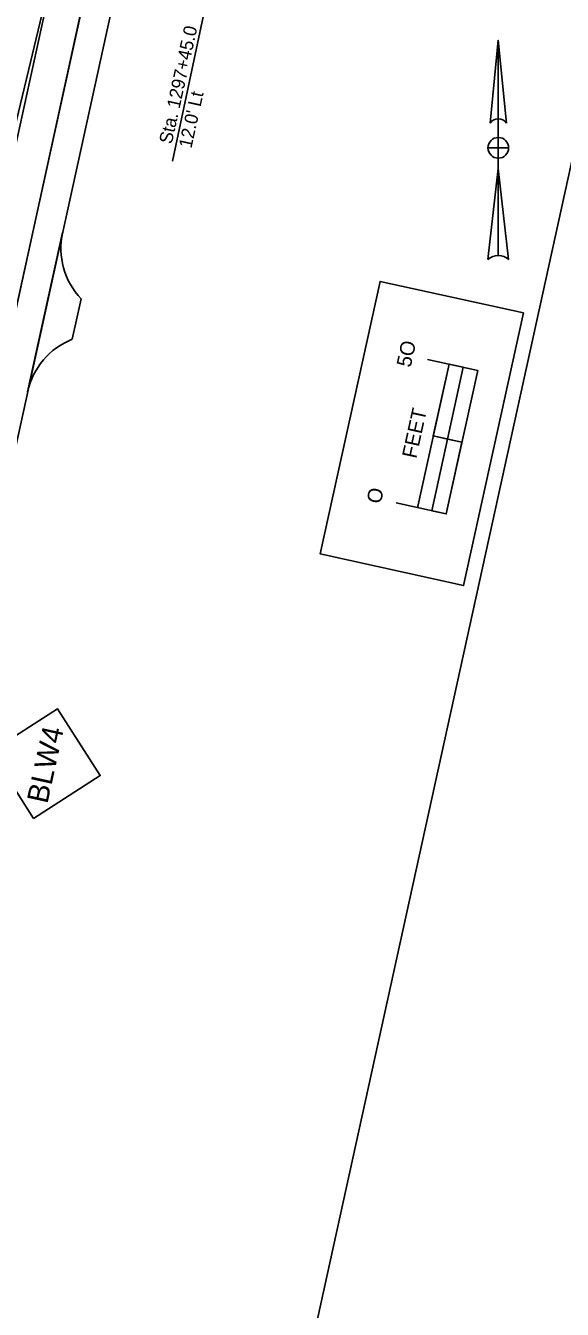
# Model space of a CAD drawing. Extents: x 14104283 to 14120882, y 8635219 to 8671666.
# Drawn here: x 14108148.5 to 14108331.3, y 8640210.4 to 8640647.3 of the extents above; entities that cross this region are included whole.
import ezdxf

# ---------------------------------------------------------------- set-up
doc = ezdxf.new("R2010")
doc.units = 0
for name, color, linetype in [('dsnCellsNorthArrow', 7, 'Continuous'), ('dsnCellsScaleBlock', 7, 'Continuous'), ('dsnNonPlotable', 7, 'Continuous'), ('dsnPaintPlaceBrokenLaneLineWhite', 7, 'Continuous'), ('dsnPaintPlaceEdgeLineRightWhite', 7, 'Continuous'), ('dsnShadingGranular', 7, 'Continuous'), ('dsnShadingPaved', 7, 'Continuous'), ('dsnStdLabel', 7, 'Continuous'), ('dsnStgShadingPrevPav', 7, 'Continuous'), ('dsnTapeRemoveChannelizingWhite', 7, 'Continuous'), ('Text', 7, 'Continuous')]:
    doc.layers.add(name, color=color, linetype=linetype)

msp = doc.modelspace()

# ---------------------------------------------------------------- linework, layer by layer
at = {"layer": 'dsnCellsNorthArrow'}
for p, q in [((14108309.48, 8640642.31), (14108312.3, 8640614.14)), ((14108309.48, 8640642.31), (14108309.48, 8640569.07)), ((14108306.66, 8640614.14), (14108306.66, 8640614.14)), ((14108306.77, 8640614.4), (14108307.3, 8640614.99)), ((14108309.48, 8640602.17), (14108309.48, 8640602.17)), ((14108305.96, 8640567.66), (14108309.48, 8640598.65))]:
    msp.add_line(p, q, dxfattribs=at)
for points in [[(14108306.66, 8640614.14), (14108309.48, 8640642.31), (14108309.48, 8640615.55)], [(14108313, 8640605.69), (14108309.48, 8640605.69), (14108309.48, 8640609.21)], [(14108309.48, 8640602.17), (14108309.48, 8640605.69), (14108305.96, 8640605.69)], [(14108309.48, 8640569.07), (14108309.48, 8640598.65), (14108313, 8640567.66)]]:
    msp.add_lwpolyline(points, dxfattribs=at)
for centre, radius, start, end in [((14108309.48, 8640612.03), 3.52, 90.0204, 143.1257), ((14108309.48, 8640612.03), 3.52, 36.8481, 90.0218), ((14108309.48, 8640605.69), 3.52, 90, 180), ((14108309.48, 8640605.69), 3.52, 0, 90), ((14108309.48, 8640605.69), 3.52, 180, 270), ((14108309.48, 8640605.69), 3.52, 270, 360), ((14108309.48, 8640563.96), 5.1, 89.9894, 133.619), ((14108309.48, 8640563.96), 5.11, 46.4021, 90.0006)]:
    msp.add_arc(centre, radius, start, end, dxfattribs=at)
at = {"layer": 'dsnCellsScaleBlock'}
msp.add_line((14108297.11, 8640505.49), (14108287.34, 8640507.63), dxfattribs=at)
msp.add_line((14108297.11, 8640505.49), (14108287.34, 8640507.63), dxfattribs=at)
for points in [[(14108297.66, 8640456.73), (14108248.83, 8640467.46), (14108269.21, 8640560.25), (14108318.05, 8640549.52)], [(14108248.83, 8640467.46), (14108269.21, 8640560.25), (14108318.05, 8640549.52), (14108297.66, 8640456.73)], [(14108297.66, 8640456.73), (14108248.83, 8640467.46), (14108269.21, 8640560.25), (14108318.05, 8640549.52)], [(14108292.19, 8640506.57), (14108297.56, 8640530.99), (14108292.71, 8640532.05), (14108287.34, 8640507.63)], [(14108291.74, 8640481.07), (14108297.11, 8640505.49), (14108292.19, 8640506.57), (14108286.83, 8640482.15)]]:
    msp.add_lwpolyline(points, close=True, dxfattribs=at)
for points in [[(14108274.65, 8640484.83), (14108291.74, 8640481.07), (14108302.48, 8640529.91), (14108285.38, 8640533.66)], [(14108281.98, 8640483.22), (14108292.71, 8640532.05)]]:
    msp.add_lwpolyline(points, dxfattribs=at)
at = {"layer": 'dsnNonPlotable'}
msp.add_lwpolyline([(14107651.31, 8639844.94), (14107987.7, 8641375.92), (14108480.93, 8641267.54), (14108144.54, 8639736.56)], close=True, dxfattribs=at)
at = {"layer": 'dsnPaintPlaceBrokenLaneLineWhite'}
msp.add_line((14108099.08, 8640397.01), (14108184.86, 8640787.53), dxfattribs=at)
at = {"layer": 'dsnPaintPlaceEdgeLineRightWhite'}
msp.add_line((14108110.8, 8640394.44), (14108196.58, 8640784.95), dxfattribs=at)
at = {"layer": 'dsnShadingGranular'}
for p, q in [((14108161.12, 8640576.89), (14108155.11, 8640549.54)), ((14108155.11, 8640549.54), (14108149.21, 8640522.69))]:
    msp.add_line(p, q, dxfattribs=at)
at = {"layer": 'dsnShadingPaved'}
msp.add_lwpolyline([(14108083.12, 8640400.52), (14108129.2, 8640590.05), (14108151.72, 8640692.57), (14108163.38, 8640689.76), (14108196.58, 8640784.95), (14108110.8, 8640394.44)], close=True, dxfattribs=at)
at = {"layer": 'dsnStdLabel'}
msp.add_lwpolyline([(14108151.2, 8640377.46), (14108173.94, 8640392.01), (14108159.39, 8640414.75), (14108136.65, 8640400.2)], close=True, dxfattribs=at)
at = {"layer": 'dsnStgShadingPrevPav'}
for p, q in [((14108161.12, 8640576.89), (14108155.11, 8640549.54)), ((14108165.86, 8640547.18), (14108167.42, 8640554.3)), ((14108155.11, 8640549.54), (14108149.21, 8640522.69)), ((14108164.4, 8640540.56), (14108165.86, 8640547.18))]:
    msp.add_line(p, q, dxfattribs=at)
msp.add_lwpolyline([(14108081.5, 8640400.87), (14108123.34, 8640591.33), (14108126.55, 8640605.98), (14108216.67, 8641016.2), (14108268.16, 8641250.61), (14108382.95, 8641773.15), (14108422.02, 8641764.57), (14108309.38, 8641251.8), (14108270.22, 8641073.55), (14108265.93, 8641054.01), (14108255.74, 8641007.62), (14108202.1, 8640763.44), (14108120.56, 8640392.29)], close=True, dxfattribs=at)
for centre, start, end in [((14108185.53, 8640571.53), 167.6114, 223.5657), ((14108173.63, 8640517.32), 111.6547, 167.6089)]:
    msp.add_arc(centre, 25, start, end, dxfattribs=at)
at = {"layer": 'dsnTapeRemoveChannelizingWhite'}
msp.add_line((14108093.19, 8640398.18), (14108163.38, 8640689.76), dxfattribs=at)
at = {"layer": 'Text'}
msp.add_lwpolyline([(14108198.5, 8640601.19), (14108211.73, 8640663.2), (14108151.72, 8640692.57)], dxfattribs=at)

# ---------------------------------------------------------------- texts
at = {"layer": 'dsnCellsScaleBlock'}
for s, p in [('5O', (14108279.62, 8640530.75)), ('FEET', (14108281.51, 8640499.73)), ('O', (14108269.42, 8640484.3))]:
    msp.add_text(s, height=5, rotation=77.6078, dxfattribs=at).set_placement(p)
at = {"layer": 'dsnStdLabel'}
msp.add_text('BLW4', height=7.2, rotation=77.6078, dxfattribs=at).set_placement((14108155.92, 8640382.2))
at = {"layer": 'Text'}
for s, height, p in [('Sta. 1297+45.0', 4.4845, (14108198.28, 8640606.77)), ("12.0' Lt", 4.484, (14108204.97, 8640605.3))]:
    msp.add_text(s, height=height, rotation=77.6078, dxfattribs=at).set_placement(p)

doc.saveas('drawing.dxf')
